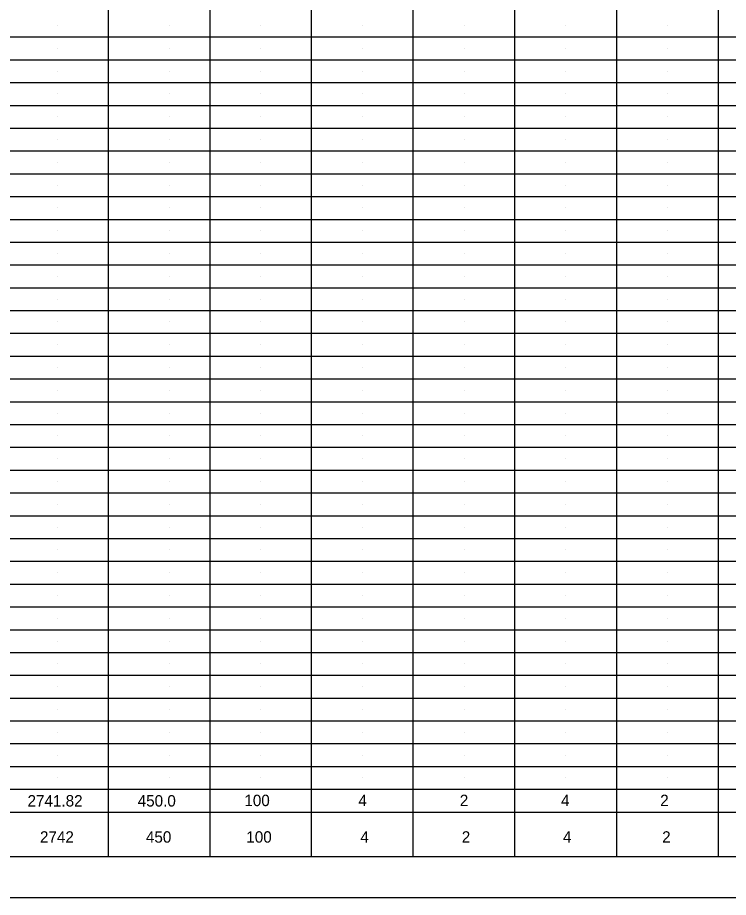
# Model space of a CAD drawing. Extents: x 2073163.9 to 2073197.9, y 634076.5 to 634098.5.
# Drawn here: x 2073172.33 to 2073181.07, y 634076.55 to 634087.36 of the extents above; entities that cross this region are included whole.
import ezdxf

# ---------------------------------------------------------------- set-up
doc = ezdxf.new("R2010")
doc.units = 0
for name, color, linetype in [('SH_Border', 7, 'Continuous'), ('SH_Cut_Line', 7, 'Continuous'), ('SH_Data', 7, 'Continuous'), ('SH_Text', 7, 'Continuous')]:
    doc.layers.add(name, color=color, linetype=linetype)

msp = doc.modelspace()

# ---------------------------------------------------------------- linework, layer by layer
at = {"layer": 'SH_Border'}
msp.add_lwpolyline([(2073165.446, 634098.05), (2073197.446, 634098.05), (2073197.446, 634077.05), (2073165.446, 634077.05)], close=True, dxfattribs=at)
at = {"layer": 'SH_Cut_Line'}
msp.add_lwpolyline([(2073163.946, 634076.55), (2073197.946, 634076.55), (2073197.946, 634098.55), (2073163.946, 634098.55)], close=True, dxfattribs=at)
at = {"layer": 'SH_Data'}
for p, q in [((2073173.451, 634077.054), (2073173.451, 634098.05)), ((2073180.946, 634077.598), (2073180.946, 634098.05)), ((2073174.701, 634077.052), (2073174.701, 634097.772)), ((2073175.946, 634077.05), (2073175.946, 634097.77)), ((2073177.196, 634077.05), (2073177.196, 634097.77)), ((2073178.446, 634077.05), (2073178.446, 634097.77)), ((2073179.696, 634077.05), (2073179.696, 634097.77)), ((2073180.946, 634077.05), (2073180.946, 634097.77)), ((2073172.821, 634087.258), (2073172.821, 634087.258)), ((2073174.196, 634087.258), (2073174.196, 634087.258)), ((2073175.321, 634087.258), (2073175.321, 634087.258)), ((2073176.571, 634087.258), (2073176.571, 634087.258)), ((2073177.821, 634087.258), (2073177.821, 634087.258)), ((2073179.071, 634087.258), (2073179.071, 634087.258)), ((2073180.321, 634087.258), (2073180.321, 634087.258)), ((2073165.446, 634087.118), (2073195.946, 634087.118)), ((2073172.821, 634086.978), (2073172.821, 634086.978)), ((2073174.196, 634086.978), (2073174.196, 634086.978)), ((2073175.321, 634086.978), (2073175.321, 634086.978)), ((2073176.571, 634086.978), (2073176.571, 634086.978)), ((2073177.821, 634086.978), (2073177.821, 634086.978)), ((2073179.071, 634086.978), (2073179.071, 634086.978)), ((2073180.321, 634086.978), (2073180.321, 634086.978)), ((2073165.446, 634086.838), (2073195.946, 634086.838)), ((2073172.821, 634086.698), (2073172.821, 634086.698)), ((2073174.196, 634086.698), (2073174.196, 634086.698)), ((2073175.321, 634086.698), (2073175.321, 634086.698)), ((2073176.571, 634086.698), (2073176.571, 634086.698)), ((2073177.821, 634086.698), (2073177.821, 634086.698)), ((2073179.071, 634086.698), (2073179.071, 634086.698)), ((2073180.321, 634086.698), (2073180.321, 634086.698)), ((2073165.446, 634086.558), (2073195.946, 634086.558)), ((2073172.821, 634086.418), (2073172.821, 634086.418)), ((2073174.196, 634086.418), (2073174.196, 634086.418)), ((2073175.321, 634086.418), (2073175.321, 634086.418)), ((2073176.571, 634086.418), (2073176.571, 634086.418)), ((2073177.821, 634086.418), (2073177.821, 634086.418)), ((2073179.071, 634086.418), (2073179.071, 634086.418)), ((2073180.321, 634086.418), (2073180.321, 634086.418)), ((2073165.446, 634086.278), (2073195.946, 634086.278)), ((2073172.821, 634086.138), (2073172.821, 634086.138)), ((2073174.196, 634086.138), (2073174.196, 634086.138)), ((2073175.321, 634086.138), (2073175.321, 634086.138)), ((2073176.571, 634086.138), (2073176.571, 634086.138)), ((2073177.821, 634086.138), (2073177.821, 634086.138)), ((2073179.071, 634086.138), (2073179.071, 634086.138)), ((2073180.321, 634086.138), (2073180.321, 634086.138)), ((2073165.446, 634085.998), (2073195.946, 634085.998)), ((2073172.821, 634085.858), (2073172.821, 634085.858)), ((2073174.196, 634085.858), (2073174.196, 634085.858)), ((2073175.321, 634085.858), (2073175.321, 634085.858)), ((2073176.571, 634085.858), (2073176.571, 634085.858)), ((2073177.821, 634085.858), (2073177.821, 634085.858)), ((2073179.071, 634085.858), (2073179.071, 634085.858)), ((2073180.321, 634085.858), (2073180.321, 634085.858)), ((2073165.446, 634085.718), (2073195.946, 634085.718)), ((2073172.821, 634085.578), (2073172.821, 634085.578)), ((2073174.196, 634085.578), (2073174.196, 634085.578)), ((2073175.321, 634085.578), (2073175.321, 634085.578)), ((2073176.571, 634085.578), (2073176.571, 634085.578)), ((2073177.821, 634085.578), (2073177.821, 634085.578)), ((2073179.071, 634085.578), (2073179.071, 634085.578)), ((2073180.321, 634085.578), (2073180.321, 634085.578)), ((2073165.446, 634085.438), (2073195.946, 634085.438)), ((2073172.821, 634085.298), (2073172.821, 634085.298)), ((2073174.196, 634085.298), (2073174.196, 634085.298)), ((2073175.321, 634085.298), (2073175.321, 634085.298)), ((2073176.571, 634085.298), (2073176.571, 634085.298)), ((2073177.821, 634085.298), (2073177.821, 634085.298)), ((2073179.071, 634085.298), (2073179.071, 634085.298)), ((2073180.321, 634085.298), (2073180.321, 634085.298)), ((2073165.446, 634085.158), (2073195.946, 634085.158)), ((2073172.821, 634085.018), (2073172.821, 634085.018)), ((2073174.196, 634085.018), (2073174.196, 634085.018)), ((2073175.321, 634085.018), (2073175.321, 634085.018)), ((2073176.571, 634085.018), (2073176.571, 634085.018)), ((2073177.821, 634085.018), (2073177.821, 634085.018)), ((2073179.071, 634085.018), (2073179.071, 634085.018)), ((2073180.321, 634085.018), (2073180.321, 634085.018)), ((2073165.446, 634084.878), (2073195.946, 634084.878)), ((2073172.821, 634084.738), (2073172.821, 634084.738)), ((2073174.196, 634084.738), (2073174.196, 634084.738)), ((2073175.321, 634084.738), (2073175.321, 634084.738)), ((2073176.571, 634084.738), (2073176.571, 634084.738)), ((2073177.821, 634084.738), (2073177.821, 634084.738)), ((2073179.071, 634084.738), (2073179.071, 634084.738)), ((2073180.321, 634084.738), (2073180.321, 634084.738)), ((2073165.446, 634084.598), (2073195.946, 634084.598)), ((2073172.821, 634084.458), (2073172.821, 634084.458)), ((2073174.196, 634084.458), (2073174.196, 634084.458)), ((2073175.321, 634084.458), (2073175.321, 634084.458)), ((2073176.571, 634084.458), (2073176.571, 634084.458)), ((2073177.821, 634084.458), (2073177.821, 634084.458)), ((2073179.071, 634084.458), (2073179.071, 634084.458)), ((2073180.321, 634084.458), (2073180.321, 634084.458)), ((2073165.446, 634084.318), (2073195.946, 634084.318)), ((2073172.821, 634084.178), (2073172.821, 634084.178)), ((2073174.196, 634084.178), (2073174.196, 634084.178)), ((2073175.321, 634084.178), (2073175.321, 634084.178)), ((2073176.571, 634084.178), (2073176.571, 634084.178)), ((2073177.821, 634084.178), (2073177.821, 634084.178)), ((2073179.071, 634084.178), (2073179.071, 634084.178)), ((2073180.321, 634084.178), (2073180.321, 634084.178)), ((2073165.446, 634084.038), (2073195.946, 634084.038)), ((2073172.821, 634083.898), (2073172.821, 634083.898)), ((2073174.196, 634083.898), (2073174.196, 634083.898)), ((2073175.321, 634083.898), (2073175.321, 634083.898)), ((2073176.571, 634083.898), (2073176.571, 634083.898)), ((2073177.821, 634083.898), (2073177.821, 634083.898)), ((2073179.071, 634083.898), (2073179.071, 634083.898)), ((2073180.321, 634083.898), (2073180.321, 634083.898)), ((2073165.446, 634083.758), (2073195.946, 634083.758)), ((2073172.821, 634083.618), (2073172.821, 634083.618)), ((2073174.196, 634083.618), (2073174.196, 634083.618)), ((2073175.321, 634083.618), (2073175.321, 634083.618)), ((2073176.571, 634083.618), (2073176.571, 634083.618)), ((2073177.821, 634083.618), (2073177.821, 634083.618)), ((2073179.071, 634083.618), (2073179.071, 634083.618)), ((2073180.321, 634083.618), (2073180.321, 634083.618)), ((2073165.446, 634083.478), (2073195.946, 634083.478)), ((2073172.821, 634083.338), (2073172.821, 634083.338)), ((2073174.196, 634083.338), (2073174.196, 634083.338)), ((2073175.321, 634083.338), (2073175.321, 634083.338)), ((2073176.571, 634083.338), (2073176.571, 634083.338)), ((2073177.821, 634083.338), (2073177.821, 634083.338)), ((2073179.071, 634083.338), (2073179.071, 634083.338)), ((2073180.321, 634083.338), (2073180.321, 634083.338)), ((2073165.446, 634083.198), (2073195.946, 634083.198)), ((2073172.821, 634083.058), (2073172.821, 634083.058)), ((2073174.196, 634083.058), (2073174.196, 634083.058)), ((2073175.321, 634083.058), (2073175.321, 634083.058)), ((2073176.571, 634083.058), (2073176.571, 634083.058)), ((2073177.821, 634083.058), (2073177.821, 634083.058)), ((2073179.071, 634083.058), (2073179.071, 634083.058)), ((2073180.321, 634083.058), (2073180.321, 634083.058)), ((2073165.446, 634082.918), (2073195.946, 634082.918)), ((2073172.821, 634082.778), (2073172.821, 634082.778)), ((2073174.196, 634082.778), (2073174.196, 634082.778)), ((2073175.321, 634082.778), (2073175.321, 634082.778)), ((2073176.571, 634082.778), (2073176.571, 634082.778)), ((2073177.821, 634082.778), (2073177.821, 634082.778)), ((2073179.071, 634082.778), (2073179.071, 634082.778)), ((2073180.321, 634082.778), (2073180.321, 634082.778)), ((2073165.446, 634082.638), (2073195.946, 634082.638)), ((2073172.821, 634082.498), (2073172.821, 634082.498)), ((2073174.196, 634082.498), (2073174.196, 634082.498)), ((2073175.321, 634082.498), (2073175.321, 634082.498)), ((2073176.571, 634082.498), (2073176.571, 634082.498)), ((2073177.821, 634082.498), (2073177.821, 634082.498)), ((2073179.071, 634082.498), (2073179.071, 634082.498)), ((2073180.321, 634082.498), (2073180.321, 634082.498)), ((2073165.446, 634082.358), (2073195.946, 634082.358)), ((2073172.821, 634082.218), (2073172.821, 634082.218)), ((2073174.196, 634082.218), (2073174.196, 634082.218)), ((2073175.321, 634082.218), (2073175.321, 634082.218)), ((2073176.571, 634082.218), (2073176.571, 634082.218)), ((2073177.821, 634082.218), (2073177.821, 634082.218)), ((2073179.071, 634082.218), (2073179.071, 634082.218)), ((2073180.321, 634082.218), (2073180.321, 634082.218)), ((2073165.446, 634082.078), (2073195.946, 634082.078)), ((2073172.821, 634081.938), (2073172.821, 634081.938)), ((2073174.196, 634081.938), (2073174.196, 634081.938)), ((2073175.321, 634081.938), (2073175.321, 634081.938)), ((2073176.571, 634081.938), (2073176.571, 634081.938)), ((2073177.821, 634081.938), (2073177.821, 634081.938)), ((2073179.071, 634081.938), (2073179.071, 634081.938)), ((2073180.321, 634081.938), (2073180.321, 634081.938)), ((2073165.446, 634081.798), (2073195.946, 634081.798)), ((2073172.821, 634081.658), (2073172.821, 634081.658)), ((2073174.196, 634081.658), (2073174.196, 634081.658)), ((2073175.321, 634081.658), (2073175.321, 634081.658)), ((2073176.571, 634081.658), (2073176.571, 634081.658)), ((2073177.821, 634081.658), (2073177.821, 634081.658)), ((2073179.071, 634081.658), (2073179.071, 634081.658)), ((2073180.321, 634081.658), (2073180.321, 634081.658)), ((2073165.446, 634081.518), (2073195.946, 634081.518)), ((2073172.821, 634081.378), (2073172.821, 634081.378)), ((2073174.196, 634081.378), (2073174.196, 634081.378)), ((2073175.321, 634081.378), (2073175.321, 634081.378)), ((2073176.571, 634081.378), (2073176.571, 634081.378)), ((2073177.821, 634081.378), (2073177.821, 634081.378)), ((2073179.071, 634081.378), (2073179.071, 634081.378)), ((2073180.321, 634081.378), (2073180.321, 634081.378)), ((2073165.446, 634081.238), (2073195.946, 634081.238)), ((2073172.821, 634081.098), (2073172.821, 634081.098)), ((2073174.196, 634081.098), (2073174.196, 634081.098)), ((2073175.321, 634081.098), (2073175.321, 634081.098)), ((2073176.571, 634081.098), (2073176.571, 634081.098)), ((2073177.821, 634081.098), (2073177.821, 634081.098)), ((2073179.071, 634081.098), (2073179.071, 634081.098)), ((2073180.321, 634081.098), (2073180.321, 634081.098)), ((2073165.446, 634080.958), (2073195.946, 634080.958)), ((2073172.821, 634080.818), (2073172.821, 634080.818)), ((2073174.196, 634080.818), (2073174.196, 634080.818)), ((2073175.321, 634080.818), (2073175.321, 634080.818)), ((2073176.571, 634080.818), (2073176.571, 634080.818)), ((2073177.821, 634080.818), (2073177.821, 634080.818)), ((2073179.071, 634080.818), (2073179.071, 634080.818)), ((2073180.321, 634080.818), (2073180.321, 634080.818)), ((2073165.446, 634080.678), (2073195.946, 634080.678)), ((2073172.821, 634080.538), (2073172.821, 634080.538)), ((2073174.196, 634080.538), (2073174.196, 634080.538)), ((2073175.321, 634080.538), (2073175.321, 634080.538)), ((2073176.571, 634080.538), (2073176.571, 634080.538)), ((2073177.821, 634080.538), (2073177.821, 634080.538)), ((2073179.071, 634080.538), (2073179.071, 634080.538)), ((2073180.321, 634080.538), (2073180.321, 634080.538)), ((2073165.446, 634080.398), (2073195.946, 634080.398)), ((2073172.821, 634080.258), (2073172.821, 634080.258)), ((2073174.196, 634080.258), (2073174.196, 634080.258)), ((2073175.321, 634080.258), (2073175.321, 634080.258)), ((2073176.571, 634080.258), (2073176.571, 634080.258)), ((2073177.821, 634080.258), (2073177.821, 634080.258)), ((2073179.071, 634080.258), (2073179.071, 634080.258)), ((2073180.321, 634080.258), (2073180.321, 634080.258)), ((2073165.446, 634080.118), (2073195.946, 634080.118)), ((2073172.821, 634079.978), (2073172.821, 634079.978)), ((2073174.196, 634079.978), (2073174.196, 634079.978)), ((2073175.321, 634079.978), (2073175.321, 634079.978)), ((2073176.571, 634079.978), (2073176.571, 634079.978)), ((2073177.821, 634079.978), (2073177.821, 634079.978)), ((2073179.071, 634079.978), (2073179.071, 634079.978)), ((2073180.321, 634079.978), (2073180.321, 634079.978)), ((2073165.446, 634079.838), (2073195.946, 634079.838)), ((2073172.821, 634079.698), (2073172.821, 634079.698)), ((2073174.196, 634079.698), (2073174.196, 634079.698)), ((2073175.321, 634079.698), (2073175.321, 634079.698)), ((2073176.571, 634079.698), (2073176.571, 634079.698)), ((2073177.821, 634079.698), (2073177.821, 634079.698)), ((2073179.071, 634079.698), (2073179.071, 634079.698)), ((2073180.321, 634079.698), (2073180.321, 634079.698)), ((2073165.446, 634079.558), (2073195.946, 634079.558)), ((2073172.821, 634079.418), (2073172.821, 634079.418)), ((2073174.196, 634079.418), (2073174.196, 634079.418)), ((2073175.321, 634079.418), (2073175.321, 634079.418)), ((2073176.571, 634079.418), (2073176.571, 634079.418)), ((2073177.821, 634079.418), (2073177.821, 634079.418)), ((2073179.071, 634079.418), (2073179.071, 634079.418)), ((2073180.321, 634079.418), (2073180.321, 634079.418)), ((2073165.446, 634079.278), (2073195.946, 634079.278)), ((2073172.821, 634079.138), (2073172.821, 634079.138)), ((2073174.196, 634079.138), (2073174.196, 634079.138)), ((2073175.321, 634079.138), (2073175.321, 634079.138)), ((2073176.571, 634079.138), (2073176.571, 634079.138)), ((2073177.821, 634079.138), (2073177.821, 634079.138)), ((2073179.071, 634079.138), (2073179.071, 634079.138)), ((2073180.321, 634079.138), (2073180.321, 634079.138)), ((2073165.446, 634078.998), (2073195.946, 634078.998)), ((2073172.821, 634078.858), (2073172.821, 634078.858)), ((2073174.196, 634078.858), (2073174.196, 634078.858)), ((2073175.321, 634078.858), (2073175.321, 634078.858)), ((2073176.571, 634078.858), (2073176.571, 634078.858)), ((2073177.821, 634078.858), (2073177.821, 634078.858)), ((2073179.071, 634078.858), (2073179.071, 634078.858)), ((2073180.321, 634078.858), (2073180.321, 634078.858)), ((2073165.446, 634078.718), (2073195.946, 634078.718)), ((2073172.821, 634078.578), (2073172.821, 634078.578)), ((2073174.196, 634078.578), (2073174.196, 634078.578)), ((2073175.321, 634078.578), (2073175.321, 634078.578)), ((2073176.571, 634078.578), (2073176.571, 634078.578)), ((2073177.821, 634078.578), (2073177.821, 634078.578)), ((2073179.071, 634078.578), (2073179.071, 634078.578)), ((2073180.321, 634078.578), (2073180.321, 634078.578)), ((2073165.446, 634078.438), (2073195.946, 634078.438)), ((2073172.821, 634078.298), (2073172.821, 634078.298)), ((2073174.196, 634078.298), (2073174.196, 634078.298)), ((2073175.321, 634078.298), (2073175.321, 634078.298)), ((2073176.571, 634078.298), (2073176.571, 634078.298)), ((2073177.821, 634078.298), (2073177.821, 634078.298)), ((2073179.071, 634078.298), (2073179.071, 634078.298)), ((2073180.321, 634078.298), (2073180.321, 634078.298)), ((2073165.446, 634078.158), (2073195.946, 634078.158)), ((2073172.821, 634078.018), (2073172.821, 634078.018)), ((2073174.196, 634078.018), (2073174.196, 634078.018)), ((2073175.321, 634078.018), (2073175.321, 634078.018)), ((2073176.571, 634078.018), (2073176.571, 634078.018)), ((2073177.821, 634078.018), (2073177.821, 634078.018)), ((2073179.071, 634078.018), (2073179.071, 634078.018)), ((2073180.321, 634078.018), (2073180.321, 634078.018)), ((2073165.446, 634077.878), (2073195.946, 634077.878)), ((2073172.821, 634077.738), (2073172.821, 634077.738)), ((2073174.196, 634077.738), (2073174.196, 634077.738)), ((2073175.321, 634077.738), (2073175.321, 634077.738)), ((2073176.571, 634077.738), (2073176.571, 634077.738)), ((2073177.821, 634077.738), (2073177.821, 634077.738)), ((2073179.071, 634077.738), (2073179.071, 634077.738)), ((2073180.321, 634077.738), (2073180.321, 634077.738)), ((2073165.446, 634077.598), (2073195.946, 634077.598)), ((2073175.321, 634077.324), (2073175.321, 634077.324)), ((2073176.571, 634077.324), (2073176.571, 634077.324)), ((2073177.821, 634077.324), (2073177.821, 634077.324)), ((2073179.071, 634077.324), (2073179.071, 634077.324)), ((2073180.321, 634077.324), (2073180.321, 634077.324))]:
    msp.add_line(p, q, dxfattribs=at)

# ---------------------------------------------------------------- texts
at = {"layer": 'SH_Text'}
for s, p in [('2741.82', (2073172.455, 634077.666)), ('450.0', (2073173.809, 634077.666)), ('100', (2073175.12, 634077.671)), ('4', (2073176.522, 634077.671)), ('2', (2073177.768, 634077.671)), ('4', (2073179.012, 634077.671)), ('2', (2073180.231, 634077.671)), ('2742', (2073172.608, 634077.222)), ('450', (2073173.91, 634077.222)), ('100', (2073175.144, 634077.222)), ('4', (2073176.546, 634077.222)), ('2', (2073177.792, 634077.222)), ('4', (2073179.036, 634077.222)), ('2', (2073180.255, 634077.222))]:
    msp.add_text(s, height=0.14, rotation=0.0001, dxfattribs=at).set_placement(p)

doc.saveas('drawing.dxf')
